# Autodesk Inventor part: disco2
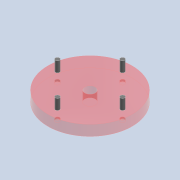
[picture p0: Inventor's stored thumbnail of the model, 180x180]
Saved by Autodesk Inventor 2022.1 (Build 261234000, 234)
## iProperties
Created: 2022-04
Part Number: disco2
Material: Generico
Document SubType Name: Modeling
Designer: Ryzen5700u
Density: 1 g/cm^3
Appearance: Default
Mass: 15.554 g
Surface Area: 79.5451 cm^2
Volume: 15.554 cm^3
Author: Ryzen5700u
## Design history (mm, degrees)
sketch "Schizzo1"
  geometry: C1 r 20 at (0, 0); 1 further point
  constraints: 1 centre point, 1 coincident
  dimensions: "d0" = 40 diameter of C1
extrude "Estrusione1" new body sketch "Schizzo1" distance "d1" = 5; taper "d2" = 0 deg
sketch "Schizzo2"
  geometry: C1 r 2.5 at (0, 0); 1 further point
  constraints: 1 centre point, 1 coincident
  dimensions: "d3" = 5 diameter of C1
extrude "Estrusione2" cut sketch "Schizzo2" extent not by distance; stored distance "d4" = 0; taper "d5" = 0 deg
sketch "Schizzo3" dims "d6" = 31
  geometry: C1 r 1 at (-15.5, 0); 2 further points
  constraints: 1 centre point, 1 coincident, 1 horizontal alignment, 2 other
  dimensions: "d7" = 2 diameter of C1
extrude "Estrusione3" new body sketch "Schizzo3" distance "d8" = 5; taper "d9" = 0 deg
pattern_circular "Serie circolare1" dims angle "d11" = 360 deg
sketch "Schizzo4"
  geometry: C1 r 2.5 at (0, 0) reference; C2 r 20 at (0, 0) reference; C3 r 1 at (-15.5, 0) reference; C4 r 1 at (0, -15.5) reference; C5 r 1 at (0, 15.5) reference; C6 r 1 at (15.5, 0) reference; 1 further point
extrude "Estrusione4" cut sketch "Schizzo4" distance "d13" = 1; taper "d14" = 0 deg
sketch "Schizzo5"
  geometry: C1 r 15.5 at (0, 0); 1 further point
  constraints: 1 centre point, 1 coincident
  dimensions: "d15" = 31 diameter of C1
feature "SupEstrusione1" sketch "Schizzo5" dims "d16" = 2, "d17" = 0
node "Solido1"
node "Linea chiusa proiettata1"
node "Superf1"
node "Solido2"
